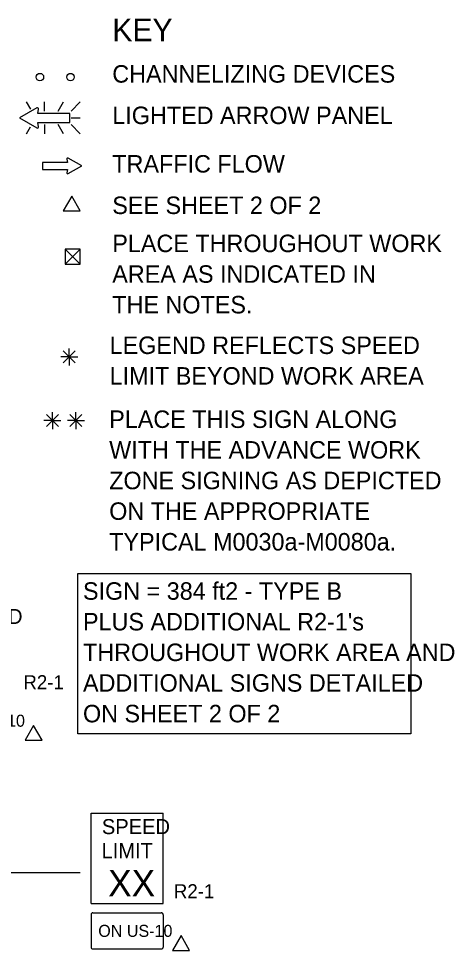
# Model space of a CAD drawing. Extents: x 16574 to 18479, y 5718 to 6974.
# Drawn here: x 17204.3 to 17436.3, y 6428 to 6923.6 of the extents above; entities that cross this region are included whole.
import ezdxf

# ---------------------------------------------------------------- set-up
doc = ezdxf.new("R2010")
doc.units = 0
for name, color, linetype in [('MT_SCRATCH_LEVEL_E', 7, 'Continuous'), ('TRAFFIC_SIGNS_PR', 7, 'Continuous'), ('TYPICAL_TEXT_DIMEN_EX', 7, 'Continuous'), ('TYPICAL_TEXT_DIMEN_PR', 7, 'Continuous')]:
    doc.layers.add(name, color=color, linetype=linetype)

msp = doc.modelspace()

# ---------------------------------------------------------------- linework, layer by layer
at = {"layer": 'MT_SCRATCH_LEVEL_E'}
for p, q in [((17230.34, 6847.14), (17217.09, 6847.14)), ((17217.09, 6847.14), (17217.09, 6843.4)), ((17230.03, 6848.91), (17230.34, 6847.14)), ((17237.95, 6845.28), (17230.71, 6849.4)), ((17230.71, 6841.14), (17237.95, 6845.28)), ((17217.09, 6843.4), (17230.34, 6843.4)), ((17230.34, 6843.4), (17230.03, 6841.62))]:
    msp.add_line(p, q, dxfattribs=at)
for centre, start, end in [((17230.49, 6848.99), 60.4248, 189.9638), ((17230.49, 6841.55), 170.0362, 299.7731)]:
    msp.add_arc(centre, 0.463, start, end, dxfattribs=at)
at = {"layer": 'TRAFFIC_SIGNS_PR'}
for p, q in [((17210.78, 6875.47), (17208.57, 6879.3)), ((17218.1, 6874.36), (17218.1, 6879.3)), ((17225.34, 6874.36), (17228.19, 6879.3)), ((17232.25, 6874.36), (17237.19, 6879.3)), ((17232.25, 6870.8), (17237.19, 6870.8)), ((17208.53, 6862.31), (17210.64, 6865.98)), ((17218.1, 6867.25), (17218.1, 6862.31)), ((17228.23, 6862.31), (17225.38, 6867.25)), ((17232.25, 6867.25), (17237.19, 6862.31)), ((17242.89, 6500.94), (17281.29, 6500.94)), ((17242.89, 6452.94), (17242.89, 6500.94)), ((17281.29, 6452.94), (17281.29, 6500.94)), ((17242.89, 6452.94), (17281.29, 6452.94)), ((17242.89, 6446.94), (17242.89, 6429.74)), ((17243.89, 6447.94), (17280.29, 6447.94)), ((17281.29, 6446.94), (17281.29, 6429.74)), ((17243.89, 6428.74), (17280.29, 6428.74))]:
    msp.add_line(p, q, dxfattribs=at)
for points in [[(17214.03, 6876.08), (17204.74, 6870.8), (17214.03, 6865.48)], [(17214.9, 6866.11), (17214.5, 6868.38), (17231.52, 6868.38), (17231.52, 6873.18), (17214.5, 6873.18), (17214.91, 6875.46)]]:
    msp.add_lwpolyline(points, dxfattribs=at)
for centre in [(17215.66, 6892.49), (17231.96, 6892.49)]:
    msp.add_circle(centre, 2, dxfattribs=at)
for centre, radius, start, end in [((17214.32, 6875.56), 0.598, 350.7308, 118.8916), ((17214.32, 6866.01), 0.597, 241.4833, 9.9593), ((17243.89, 6446.94), 1, 90, 180), ((17280.29, 6446.94), 1, 0, 90), ((17243.89, 6429.74), 1, 180, 270), ((17280.29, 6429.74), 1, 270, 0)]:
    msp.add_arc(centre, radius, start, end, dxfattribs=at)
at = {"layer": 'TYPICAL_TEXT_DIMEN_EX'}
msp.add_lwpolyline([(17235.92, 6628.43), (17413.13, 6628.43), (17413.13, 6543.16), (17235.92, 6543.16)], close=True, dxfattribs=at)
at = {"layer": 'TYPICAL_TEXT_DIMEN_PR'}
for p, q in [((17229.19, 6800.9), (17237.19, 6792.9)), ((17229.19, 6792.9), (17237.19, 6800.9)), ((17228.14, 6746.86), (17234.52, 6740.48)), ((17234.52, 6746.86), (17228.14, 6740.48)), ((17231.33, 6743.67), (17231.33, 6748.13)), ((17231.33, 6743.67), (17226.8, 6743.67)), ((17231.33, 6743.67), (17234.52, 6743.67)), ((17231.33, 6743.67), (17235.81, 6743.67)), ((17231.33, 6743.67), (17231.33, 6739.17)), ((17219.14, 6712.99), (17225.51, 6706.61)), ((17225.51, 6712.99), (17219.14, 6706.61)), ((17222.33, 6709.8), (17222.33, 6714.25)), ((17231.69, 6712.99), (17238.07, 6706.61)), ((17238.07, 6712.99), (17231.69, 6706.61)), ((17234.88, 6709.8), (17234.88, 6714.25)), ((17222.33, 6709.8), (17217.79, 6709.8)), ((17222.33, 6709.8), (17225.51, 6709.8)), ((17222.33, 6709.8), (17226.8, 6709.8)), ((17222.33, 6709.8), (17222.33, 6705.3)), ((17234.88, 6709.8), (17230.35, 6709.8)), ((17234.88, 6709.8), (17238.07, 6709.8)), ((17234.88, 6709.8), (17239.36, 6709.8)), ((17234.88, 6709.8), (17234.88, 6705.3)), ((17080.65, 6469.33), (17237.03, 6469.33))]:
    msp.add_line(p, q, dxfattribs=at)
for points in [[(17232.66, 6829.11), (17228.14, 6821.28), (17237.19, 6821.28)], [(17229.19, 6800.9), (17229.19, 6792.9), (17237.19, 6792.9), (17237.19, 6800.9)], [(17212.34, 6547.6), (17207.82, 6539.77), (17216.87, 6539.77)], [(17290.84, 6435.8), (17286.31, 6427.97), (17295.36, 6427.97)]]:
    msp.add_lwpolyline(points, close=True, dxfattribs=at)

# ---------------------------------------------------------------- texts
at = {"layer": 'TRAFFIC_SIGNS_PR'}
for s, height, p in [('PLACE THROUGHOUT WORK', 9.3, (17254.2, 6799.39)), ('AREA AS INDICATED IN', 9.3, (17254.2, 6783.09)), ('THE NOTES.', 9.3, (17254.2, 6766.79)), ('PLACE THIS SIGN ALONG', 9.3, (17252.56, 6705.87)), ('WITH THE ADVANCE WORK', 9.3, (17252.56, 6689.57)), ('ZONE SIGNING AS DEPICTED', 9.3, (17252.56, 6673.27)), ('ON THE APPROPRIATE', 9.3, (17252.56, 6656.97)), ('TYPICAL M0030a-M0080a.', 9.3, (17252.56, 6640.67)), ('SPEED', 8, (17170.16, 6601.6)), ('R2-1', 7.44, (17206.86, 6566.91)), ('ON US-10', 6.4, (17168.23, 6546.94)), ('SPEED', 8, (17248.66, 6489.8)), ('LIMIT', 8, (17248.49, 6477)), ('XX', 14.031, (17252, 6456.7)), ('R2-1', 7.44, (17286.97, 6455.73)), ('ON US-10', 6.4, (17246.73, 6435.14))]:
    msp.add_text(s, height=height, dxfattribs=at).set_placement(p)
at = {"layer": 'TYPICAL_TEXT_DIMEN_EX'}
for s, height, p in [('KEY', 12, (17254.2, 6911.6)), ('CHANNELIZING DEVICES', 9.3, (17254.2, 6889.55)), ('LIGHTED ARROW PANEL', 9.3, (17254.2, 6867.5)), ('TRAFFIC FLOW', 9.3, (17254.2, 6841.7)), ('SEE SHEET 2 OF 2', 9.3, (17254.2, 6819.65)), ('LEGEND REFLECTS SPEED', 9.3, (17252.78, 6745.2)), ('LIMIT BEYOND WORK AREA', 9.3, (17252.78, 6728.9)), ('SIGN = 384 ft2 - TYPE B', 9.3, (17238.61, 6614.47)), ("PLUS ADDITIONAL R2-1's", 9.3, (17238.61, 6598.16)), ('THROUGHOUT WORK AREA AND', 9.3, (17238.61, 6581.86)), ('ADDITIONAL SIGNS DETAILED', 9.3, (17238.61, 6565.57)), ('ON SHEET 2 OF 2', 9.3, (17238.61, 6549.27))]:
    msp.add_text(s, height=height, dxfattribs=at).set_placement(p)

doc.saveas('drawing.dxf')
